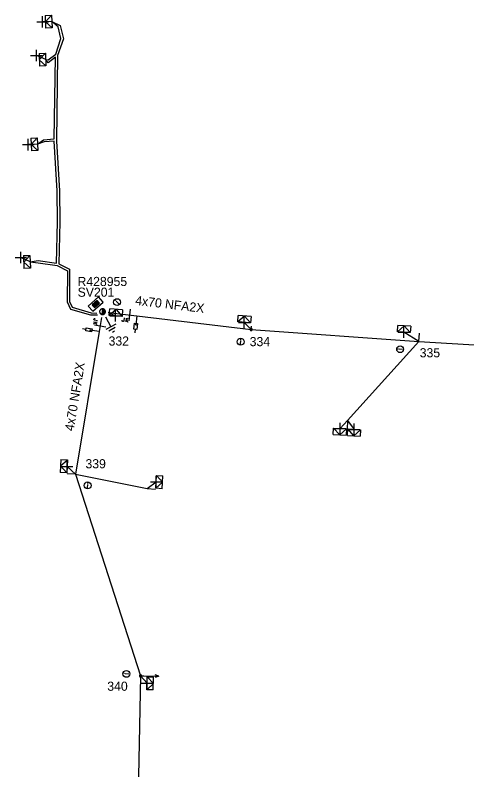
# Model space of a CAD drawing. Extents: x -540466 to -537383, y -1184038 to -1179972.
# Drawn here: x -538044.7 to -537995.3, y -1180805.5 to -1180723 of the extents above; entities that cross this region are included whole.
import ezdxf

# ---------------------------------------------------------------- set-up
doc = ezdxf.new("R2010")
doc.units = 0
for name, color, linetype in [('Vrstva 1', 7, 'Continuous'), ('Vrstva 10', 7, 'Continuous'), ('Vrstva 13', 7, 'Continuous'), ('Vrstva 14', 7, 'Continuous'), ('Vrstva 15', 7, 'Continuous'), ('Vrstva 16', 7, 'Continuous'), ('Vrstva 18', 7, 'Continuous'), ('Vrstva 2', 7, 'Continuous'), ('Vrstva 28', 7, 'Continuous'), ('Vrstva 29', 7, 'Continuous'), ('Vrstva 30', 7, 'Continuous'), ('Vrstva 31', 7, 'Continuous'), ('Vrstva 34', 7, 'Continuous'), ('Vrstva 36', 7, 'Continuous'), ('Vrstva 5', 7, 'Continuous'), ('Vrstva 50', 7, 'Continuous'), ('Vrstva 51', 7, 'Continuous'), ('Vrstva 59', 7, 'Continuous'), ('Vrstva 8', 7, 'Continuous'), ('Vrstva 9', 7, 'Continuous')]:
    doc.layers.add(name, color=color, linetype=linetype)

# ---------------------------------------------------------------- blocks, each defined once
blk = doc.blocks.new('NN440')
at = {"layer": 'Vrstva 2'}
for points in [[(0.63, 0), (0.63, 0.06), (0.62, 0.13), (0.6, 0.19), (0.58, 0.25), (0.55, 0.31), (0.51, 0.37), (0.47, 0.42), (0.42, 0.46), (0.37, 0.51), (0.32, 0.54), (0.26, 0.57), (0.2, 0.59), (0.13, 0.61), (0.07, 0.62), (0, 0.63), (-0.06, 0.62), (-0.13, 0.61), (-0.19, 0.59), (-0.26, 0.57), (-0.31, 0.54), (-0.37, 0.51), (-0.42, 0.46), (-0.47, 0.42), (-0.51, 0.37), (-0.54, 0.31), (-0.57, 0.25), (-0.6, 0.19), (-0.62, 0.13), (-0.63, 0.06), (-0.63, 0), (-0.63, -0.07), (-0.62, -0.14), (-0.6, -0.2), (-0.57, -0.26), (-0.54, -0.32), (-0.51, -0.37), (-0.47, -0.43), (-0.42, -0.47), (-0.37, -0.51), (-0.31, -0.55), (-0.26, -0.58), (-0.19, -0.6), (-0.13, -0.62), (-0.06, -0.63), (0, -0.63), (0.07, -0.63), (0.13, -0.62), (0.2, -0.6), (0.26, -0.58), (0.32, -0.55), (0.37, -0.51), (0.42, -0.47), (0.47, -0.43), (0.51, -0.37), (0.55, -0.32), (0.58, -0.26), (0.6, -0.2), (0.62, -0.14), (0.63, -0.07), (0.63, 0)], [(-0.63, 0), (0.63, 0)], [(-0.6, -0.18), (0.57, -0.18)], [(-0.51, -0.32), (0.5, -0.32)], [(-0.37, -0.47), (0.35, -0.47)]]:
    blk.add_lwpolyline(points, dxfattribs=at)
blk = doc.blocks.new('NN560')
at = {"layer": 'Vrstva 2'}
for points in [[(1.999, -0.001), (1.59, 0.141)], [(0, -0.001), (1.999, -0.001)], [(1.999, -0.001), (1.59, -0.134)]]:
    blk.add_lwpolyline(points, dxfattribs=at)
blk = doc.blocks.new('NN840')
at = {"layer": 'Vrstva 15'}
for points in [[(0.003, 0.619), (0.003, -0.631)], [(-0.745, -0.71), (-0.745, -0.66)], [(-0.73, -0.764), (-0.745, -0.71)], [(-0.657, -0.798), (-0.73, -0.764)], [(-0.627, -0.798), (-0.657, -0.798)], [(-0.558, -0.764), (-0.627, -0.798)], [(-0.538, -0.71), (-0.558, -0.764)], [(-0.538, -0.385), (-0.538, -0.71)], [(-0.332, -0.385), (-0.332, -0.798)], [(-0.332, -0.641), (-0.125, -0.385)], [(-0.263, -0.557), (-0.091, -0.798)]]:
    blk.add_lwpolyline(points, dxfattribs=at)
blk = doc.blocks.new('NN770')
at = {"layer": 'Vrstva 10'}
for p, q in [((0.002, 0.187), (0.002, 0.263)), ((0.002, -0.276), (0.002, 0.111))]:
    blk.add_line(p, q, dxfattribs=at)
blk.add_circle((0, -0.008), 0.375, dxfattribs=at)
blk = doc.blocks.new('NN800')
at = {"layer": 'Vrstva 1'}
for points in [[(-0.442, 0.442), (0.442, -0.442)], [(-0.442, -0.442), (0.442, 0.442)]]:
    blk.add_lwpolyline(points, dxfattribs=at)
blk = doc.blocks.new('NN820')
at = {"layer": 'Vrstva 13'}
for points in [[(-0.003, 0.004), (-0.003, -1.049)], [(-0.165, -0.813), (0.165, -0.813)], [(-0.165, -1.473), (-0.165, -0.813)], [(0.165, -0.813), (0.165, -1.473)], [(0.165, -1.473), (-0.165, -1.473)], [(-0.003, -1.049), (-0.062, -0.926)], [(-0.003, -1.049), (0.057, -0.926)], [(-0.003, -1.473), (-0.003, -1.871)]]:
    blk.add_lwpolyline(points, dxfattribs=at)
blk = doc.blocks.new('NN620')
at = {"layer": 'Vrstva 8'}
for points in [[(0.752, 0.004), (-0.748, 0.004)], [(-0.748, 0.004), (-0.748, -0.746)], [(0.752, -0.746), (0.752, 0.004)], [(-0.748, -0.746), (0.752, -0.746)], [(0.368, -0.18), (-0.376, -0.18)], [(-0.376, -0.18), (-0.376, -0.558)], [(-0.376, -0.558), (0.368, -0.558)], [(0.321, -0.227), (-0.329, -0.227)], [(-0.329, -0.227), (-0.329, -0.51)], [(-0.329, -0.51), (0.321, -0.51)], [(0.274, -0.274), (-0.281, -0.274)], [(-0.281, -0.274), (-0.281, -0.463)], [(-0.281, -0.463), (0.274, -0.463)], [(0.227, -0.321), (-0.234, -0.321)], [(-0.234, -0.321), (-0.234, -0.416)], [(-0.234, -0.416), (0.227, -0.416)], [(-0.193, -0.369), (0.185, -0.369)], [(0.227, -0.416), (0.227, -0.321)], [(0.274, -0.463), (0.274, -0.274)], [(0.321, -0.51), (0.321, -0.227)], [(0.368, -0.558), (0.368, -0.18)]]:
    blk.add_lwpolyline(points, dxfattribs=at)
blk = doc.blocks.new('NN630')
at = {"layer": 'Vrstva 9'}
for points in [[(-0.003, -0.7), (-0.703, 0)], [(-0.703, -0.7), (-0.703, 0), (0.697, 0), (0.697, -0.7)], [(-0.703, -0.7), (0.697, -0.7)], [(-0.003, -0.7), (0.697, 0)]]:
    blk.add_lwpolyline(points, dxfattribs=at)
blk = doc.blocks.new('NN810')
at = {"layer": 'Vrstva 14'}
for points in [[(0.004, -0.64), (0.004, -1.89)], [(0.629, -1.89), (-0.621, -1.89)], [(0.388, -2.2), (-0.399, -2.2)], [(0.004, -2.515), (-0.124, -2.515)], [(0.137, -2.515), (0.004, -2.515)]]:
    blk.add_lwpolyline(points, dxfattribs=at)
blk = doc.blocks.new('NN500')
at = {"layer": 'Vrstva 2'}
for points in [[(0, -0.24), (0.02, -0.23), (0.05, -0.23), (0.07, -0.22), (0.09, -0.22), (0.12, -0.2), (0.14, -0.19), (0.16, -0.18), (0.17, -0.16), (0.19, -0.14), (0.2, -0.12), (0.21, -0.1), (0.22, -0.07), (0.23, -0.05), (0.23, -0.02), (0.23, 0), (0.23, 0.02), (0.23, 0.05), (0.22, 0.07), (0.21, 0.1), (0.2, 0.12), (0.19, 0.14), (0.17, 0.16), (0.16, 0.17), (0.14, 0.19), (0.12, 0.2), (0.09, 0.21), (0.07, 0.22), (0.05, 0.23), (0.02, 0.23), (0, 0.23), (-0.03, 0.23), (-0.05, 0.23), (-0.07, 0.22), (-0.1, 0.21), (-0.12, 0.2), (-0.14, 0.19), (-0.16, 0.17), (-0.18, 0.16), (-0.19, 0.14), (-0.2, 0.12), (-0.22, 0.1), (-0.22, 0.07), (-0.23, 0.05), (-0.23, 0.02), (-0.24, 0), (-0.23, -0.02), (-0.23, -0.05), (-0.22, -0.07), (-0.22, -0.1), (-0.2, -0.12), (-0.19, -0.14), (-0.18, -0.16), (-0.16, -0.18), (-0.14, -0.19), (-0.12, -0.2), (-0.1, -0.22), (-0.07, -0.22), (-0.05, -0.23), (-0.03, -0.23), (0, -0.24)], [(0, -0.24), (0.02, -0.23), (0.05, -0.23), (0.07, -0.22), (0.09, -0.22), (0.12, -0.2), (0.14, -0.19), (0.16, -0.18), (0.17, -0.16), (0.19, -0.14), (0.2, -0.12), (0.21, -0.1), (0.22, -0.07), (0.23, -0.05), (0.23, -0.02), (0.23, 0), (0.23, 0.02), (0.23, 0.05), (0.22, 0.07), (0.21, 0.1), (0.2, 0.12), (0.19, 0.14), (0.17, 0.16), (0.16, 0.17), (0.14, 0.19), (0.12, 0.2), (0.09, 0.21), (0.07, 0.22), (0.05, 0.23), (0.02, 0.23), (0, 0.23), (-0.03, 0.23), (-0.05, 0.23), (-0.07, 0.22), (-0.1, 0.21), (-0.12, 0.2), (-0.14, 0.19), (-0.16, 0.17), (-0.18, 0.16), (-0.19, 0.14), (-0.2, 0.12), (-0.22, 0.1), (-0.22, 0.07), (-0.23, 0.05), (-0.23, 0.02), (-0.24, 0), (-0.23, -0.02), (-0.23, -0.05), (-0.22, -0.07), (-0.22, -0.1), (-0.2, -0.12), (-0.19, -0.14), (-0.18, -0.16), (-0.16, -0.18), (-0.14, -0.19), (-0.12, -0.2), (-0.1, -0.22), (-0.07, -0.22), (-0.05, -0.23), (-0.03, -0.23), (0, -0.24)], [(0, -0.21), (0.02, -0.2), (0.04, -0.2), (0.06, -0.2), (0.08, -0.19), (0.1, -0.18), (0.12, -0.17), (0.14, -0.15), (0.15, -0.14), (0.16, -0.12), (0.18, -0.1), (0.19, -0.08), (0.19, -0.06), (0.2, -0.04), (0.2, -0.02), (0.2, 0), (0.2, 0.02), (0.2, 0.04), (0.19, 0.06), (0.19, 0.08), (0.18, 0.1), (0.16, 0.12), (0.15, 0.14), (0.14, 0.15), (0.12, 0.17), (0.1, 0.18), (0.08, 0.19), (0.06, 0.19), (0.04, 0.2), (0.02, 0.2), (0, 0.2), (-0.02, 0.2), (-0.04, 0.2), (-0.06, 0.19), (-0.08, 0.19), (-0.1, 0.18), (-0.12, 0.17), (-0.14, 0.15), (-0.15, 0.14), (-0.17, 0.12), (-0.18, 0.1), (-0.19, 0.08), (-0.2, 0.06), (-0.2, 0.04), (-0.21, 0.02), (-0.21, 0), (-0.21, -0.02), (-0.2, -0.04), (-0.2, -0.06), (-0.19, -0.08), (-0.18, -0.1), (-0.17, -0.12), (-0.15, -0.14), (-0.14, -0.15), (-0.12, -0.17), (-0.1, -0.18), (-0.08, -0.19), (-0.06, -0.2), (-0.04, -0.2), (-0.02, -0.2), (0, -0.21)], [(0, -0.18), (0.02, -0.18), (0.04, -0.17), (0.05, -0.17), (0.07, -0.16), (0.09, -0.15), (0.1, -0.14), (0.12, -0.13), (0.13, -0.12), (0.14, -0.1), (0.15, -0.09), (0.16, -0.07), (0.17, -0.05), (0.17, -0.04), (0.17, -0.02), (0.17, 0), (0.17, 0.02), (0.17, 0.04), (0.17, 0.05), (0.16, 0.07), (0.15, 0.09), (0.14, 0.1), (0.13, 0.12), (0.12, 0.13), (0.1, 0.14), (0.09, 0.15), (0.07, 0.16), (0.05, 0.17), (0.04, 0.17), (0.02, 0.17), (0, 0.18), (-0.02, 0.17), (-0.04, 0.17), (-0.06, 0.17), (-0.07, 0.16), (-0.09, 0.15), (-0.1, 0.14), (-0.12, 0.13), (-0.13, 0.12), (-0.14, 0.1), (-0.15, 0.09), (-0.16, 0.07), (-0.17, 0.05), (-0.17, 0.04), (-0.18, 0.02), (-0.18, 0), (-0.18, -0.02), (-0.17, -0.04), (-0.17, -0.05), (-0.16, -0.07), (-0.15, -0.09), (-0.14, -0.1), (-0.13, -0.12), (-0.12, -0.13), (-0.1, -0.14), (-0.09, -0.15), (-0.07, -0.16), (-0.06, -0.17), (-0.04, -0.17), (-0.02, -0.18), (0, -0.18)], [(0, -0.15), (0.01, -0.15), (0.03, -0.14), (0.04, -0.14), (0.06, -0.13), (0.07, -0.13), (0.08, -0.12), (0.1, -0.11), (0.11, -0.1), (0.12, -0.09), (0.13, -0.07), (0.13, -0.06), (0.14, -0.05), (0.14, -0.03), (0.14, -0.02), (0.14, 0), (0.14, 0.01), (0.14, 0.03), (0.14, 0.04), (0.13, 0.06), (0.13, 0.07), (0.12, 0.09), (0.11, 0.1), (0.1, 0.11), (0.08, 0.12), (0.07, 0.13), (0.06, 0.13), (0.04, 0.14), (0.03, 0.14), (0.01, 0.14), (0, 0.15), (-0.02, 0.14), (-0.03, 0.14), (-0.05, 0.14), (-0.06, 0.13), (-0.07, 0.13), (-0.09, 0.12), (-0.1, 0.11), (-0.11, 0.1), (-0.12, 0.09), (-0.13, 0.07), (-0.13, 0.06), (-0.14, 0.04), (-0.14, 0.03), (-0.15, 0.01), (-0.15, 0), (-0.15, -0.02), (-0.14, -0.03), (-0.14, -0.05), (-0.13, -0.06), (-0.13, -0.07), (-0.12, -0.09), (-0.11, -0.1), (-0.1, -0.11), (-0.09, -0.12), (-0.07, -0.13), (-0.06, -0.13), (-0.05, -0.14), (-0.03, -0.14), (-0.02, -0.15), (0, -0.15)], [(0, -0.12), (0.01, -0.12), (0.02, -0.11), (0.03, -0.11), (0.05, -0.11), (0.06, -0.1), (0.07, -0.09), (0.08, -0.09), (0.09, -0.08), (0.09, -0.07), (0.1, -0.06), (0.11, -0.05), (0.11, -0.04), (0.11, -0.02), (0.11, -0.01), (0.12, 0), (0.11, 0.01), (0.11, 0.02), (0.11, 0.04), (0.11, 0.05), (0.1, 0.06), (0.09, 0.07), (0.09, 0.08), (0.08, 0.09), (0.07, 0.09), (0.06, 0.1), (0.05, 0.11), (0.03, 0.11), (0.02, 0.11), (0.01, 0.12), (0, 0.12), (-0.01, 0.12), (-0.03, 0.11), (-0.04, 0.11), (-0.05, 0.11), (-0.06, 0.1), (-0.07, 0.09), (-0.08, 0.09), (-0.09, 0.08), (-0.1, 0.07), (-0.1, 0.06), (-0.11, 0.05), (-0.11, 0.04), (-0.12, 0.02), (-0.12, 0.01), (-0.12, 0), (-0.12, -0.01), (-0.12, -0.02), (-0.11, -0.04), (-0.11, -0.05), (-0.1, -0.06), (-0.1, -0.07), (-0.09, -0.08), (-0.08, -0.09), (-0.07, -0.09), (-0.06, -0.1), (-0.05, -0.11), (-0.04, -0.11), (-0.03, -0.11), (-0.01, -0.12), (0, -0.12)], [(0, -0.09), (0.01, -0.09), (0.02, -0.09), (0.03, -0.08), (0.03, -0.08), (0.04, -0.08), (0.05, -0.07), (0.06, -0.07), (0.06, -0.06), (0.07, -0.05), (0.07, -0.04), (0.08, -0.04), (0.08, -0.03), (0.08, -0.02), (0.09, -0.01), (0.09, 0), (0.09, 0.01), (0.08, 0.02), (0.08, 0.03), (0.08, 0.03), (0.07, 0.04), (0.07, 0.05), (0.06, 0.06), (0.06, 0.06), (0.05, 0.07), (0.04, 0.07), (0.03, 0.08), (0.03, 0.08), (0.02, 0.08), (0.01, 0.09), (0, 0.09), (-0.01, 0.09), (-0.02, 0.08), (-0.03, 0.08), (-0.04, 0.08), (-0.04, 0.07), (-0.05, 0.07), (-0.06, 0.06), (-0.07, 0.06), (-0.07, 0.05), (-0.08, 0.04), (-0.08, 0.03), (-0.08, 0.03), (-0.09, 0.02), (-0.09, 0.01), (-0.09, 0), (-0.09, -0.01), (-0.09, -0.02), (-0.08, -0.03), (-0.08, -0.04), (-0.08, -0.04), (-0.07, -0.05), (-0.07, -0.06), (-0.06, -0.07), (-0.05, -0.07), (-0.04, -0.08), (-0.04, -0.08), (-0.03, -0.08), (-0.02, -0.09), (-0.01, -0.09), (0, -0.09)], [(0, -0.06), (0, -0.06), (0.01, -0.06), (0.02, -0.05), (0.02, -0.05), (0.03, -0.05), (0.03, -0.05), (0.04, -0.04), (0.04, -0.04), (0.05, -0.03), (0.05, -0.03), (0.05, -0.02), (0.05, -0.02), (0.05, -0.01), (0.06, -0.01), (0.06, 0), (0.06, 0.01), (0.05, 0.01), (0.05, 0.02), (0.05, 0.02), (0.05, 0.03), (0.05, 0.03), (0.04, 0.04), (0.04, 0.04), (0.03, 0.05), (0.03, 0.05), (0.02, 0.05), (0.02, 0.05), (0.01, 0.06), (0, 0.06), (0, 0.06), (-0.01, 0.06), (-0.01, 0.06), (-0.02, 0.05), (-0.02, 0.05), (-0.03, 0.05), (-0.03, 0.05), (-0.04, 0.04), (-0.04, 0.04), (-0.05, 0.03), (-0.05, 0.03), (-0.05, 0.02), (-0.06, 0.02), (-0.06, 0.01), (-0.06, 0.01), (-0.06, 0), (-0.06, -0.01), (-0.06, -0.01), (-0.06, -0.02), (-0.05, -0.02), (-0.05, -0.03), (-0.05, -0.03), (-0.04, -0.04), (-0.04, -0.04), (-0.03, -0.05), (-0.03, -0.05), (-0.02, -0.05), (-0.02, -0.05), (-0.01, -0.06), (-0.01, -0.06), (0, -0.06)], [(0, -0.03), (0, -0.03), (0, -0.03), (0.01, -0.03), (0.01, -0.03), (0.01, -0.02), (0.02, -0.02), (0.02, -0.02), (0.02, -0.02), (0.02, -0.02), (0.02, -0.01), (0.02, -0.01), (0.03, -0.01), (0.03, -0.01), (0.03, 0), (0.03, 0), (0.03, 0), (0.03, 0.01), (0.03, 0.01), (0.02, 0.01), (0.02, 0.01), (0.02, 0.02), (0.02, 0.02), (0.02, 0.02), (0.02, 0.02), (0.01, 0.02), (0.01, 0.02), (0.01, 0.03), (0, 0.03), (0, 0.03), (0, 0.03), (0, 0.03), (-0.01, 0.03), (-0.01, 0.03), (-0.01, 0.02), (-0.02, 0.02), (-0.02, 0.02), (-0.02, 0.02), (-0.02, 0.02), (-0.02, 0.02), (-0.03, 0.01), (-0.03, 0.01), (-0.03, 0.01), (-0.03, 0.01), (-0.03, 0), (-0.03, 0), (-0.03, 0), (-0.03, -0.01), (-0.03, -0.01), (-0.03, -0.01), (-0.03, -0.01), (-0.02, -0.02), (-0.02, -0.02), (-0.02, -0.02), (-0.02, -0.02), (-0.02, -0.02), (-0.01, -0.03), (-0.01, -0.03), (-0.01, -0.03), (0, -0.03), (0, -0.03)], [(0.23, 0), (0.7, 0)]]:
    blk.add_lwpolyline(points, dxfattribs=at)
blk = doc.blocks.new('NN510')
at = {"layer": 'Vrstva 2'}
blk.add_lwpolyline([(0.001, 0.002), (0.001, 0.939)], dxfattribs=at)

msp = doc.modelspace()

# ---------------------------------------------------------------- linework, layer by layer
at = {"layer": 'Vrstva 5'}
for points in [[(-538041.31, -1180727.84), (-538041.035, -1180727.876), (-538040.216, -1180727.244), (-538039.64, -1180725.544), (-538039.94, -1180724.268), (-538040.647, -1180723.681), (-538039.72, -1180724.112), (-538039.38, -1180725.556), (-538040.004, -1180727.396), (-538040.127, -1180736.746), (-538039.815, -1180742.186), (-538039.775, -1180745.591), (-538039.873, -1180750.165), (-538038.69, -1180750.77), (-538038.705, -1180754.273), (-538038.41, -1180754.906), (-538036.352, -1180755.518), (-538035.717, -1180755.55)], [(-538043.013, -1180749.952), (-538042.123, -1180749.805), (-538040.122, -1180750.096), (-538040.025, -1180745.589), (-538040.065, -1180742.194), (-538040.366, -1180736.771), (-538041.466, -1180736.843), (-538042.21, -1180737.08), (-538041.534, -1180736.597), (-538040.373, -1180736.514), (-538040.243, -1180727.573), (-538041.025, -1180728.184), (-538041.31, -1180727.84)], [(-538043.013, -1180749.952), (-538042.137, -1180750.055), (-538040.04, -1180750.36), (-538038.916, -1180750.945), (-538038.955, -1180754.327), (-538038.59, -1180755.114), (-538036.408, -1180755.762), (-538035.63, -1180755.758)]]:
    msp.add_lwpolyline(points, dxfattribs=at)
at = {"layer": 'Vrstva 50'}
for points in [[(-538034.468, -1180755.477), (-538031.337, -1180755.85), (-538018.847, -1180757.341), (-538000.519, -1180758.677), (-537985.932, -1180759.534)], [(-538035.202, -1180756.021), (-538035.459, -1180757.579), (-538038.038, -1180773.166), (-538030.938, -1180795.212), (-538031.319, -1180813.535), (-538031.082, -1180834.986)]]:
    msp.add_lwpolyline(points, dxfattribs=at)
at = {"layer": 'Vrstva 59'}
for points in [[(-538040.647, -1180723.681), (-538041.646, -1180723.726)], [(-538041.31, -1180727.84), (-538042.331, -1180727.386)], [(-538042.21, -1180737.08), (-538043.208, -1180737.141)], [(-538043.013, -1180749.952), (-538044.03, -1180749.488)], [(-538008.304, -1180767.291), (-538009.13, -1180768.174)], [(-538008.304, -1180767.291), (-538007.579, -1180768.264)]]:
    msp.add_lwpolyline(points, dxfattribs=at)
at = {"layer": 'Vrstva 8'}
for points in [[(-538034.468, -1180755.477), (-538033.666, -1180755.855)], [(-538018.847, -1180757.341), (-538019.615, -1180756.572)], [(-538000.519, -1180758.677), (-538002.15, -1180757.64)], [(-538000.519, -1180758.677), (-538008.304, -1180767.291)], [(-538038.038, -1180773.166), (-538038.978, -1180772.307)], [(-538038.038, -1180773.166), (-538030.235, -1180774.743), (-538029.237, -1180774.002)], [(-538030.938, -1180795.212), (-538030.231, -1180796.016)]]:
    msp.add_lwpolyline(points, dxfattribs=at)

# ---------------------------------------------------------------- block references
at = {"layer": 'Vrstva 13'}
for name, p, xscale, yscale, rotation in [('NN440', (-538035.1, -1180755.402), 0.5, 0.49999999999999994, 82.11889440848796), ('NN500', (-538018.847, -1180757.341), 0.5000000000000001, 0.5, 85.73899999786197), ('NN500', (-538030.938, -1180795.212), 0.49999999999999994, 0.5000000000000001, -1.2830000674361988)]:
    msp.add_blockref(name, p, dxfattribs=dict(at, xscale=xscale, yscale=yscale, rotation=rotation))
for name, p, rotation in [('NN510', (-538000.52, -1180758.677), -3.3748166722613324), ('NN510', (-538008.303, -1180767.291), 176.62620553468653), ('NN510', (-538038.037, -1180773.166), 86.772808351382), ('NN510', (-538030.235, -1180774.742), -93.71436383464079), ('NN560', (-538030.938, -1180795.212), -1.2833972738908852)]:
    msp.add_blockref(name, p, dxfattribs=dict(at, rotation=rotation))
at = {"layer": 'Vrstva 15', "rotation": 28.64399734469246}
msp.add_blockref('NN810', (-538035.1, -1180755.402), dxfattribs=at)
at = {"layer": 'Vrstva 16'}
for p, rotation in [((-538031.337, -1180755.85), -6.804733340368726), ((-538035.459, -1180757.579), -99.39240003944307)]:
    msp.add_blockref('NN820', p, dxfattribs=dict(at, rotation=rotation))
at = {"layer": 'Vrstva 18'}
for p, rotation in [((-538032.137, -1180755.755), -6.804733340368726), ((-538035.361, -1180756.986), -99.39240001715)]:
    msp.add_blockref('NN840', p, dxfattribs=dict(at, rotation=rotation))
at = {"layer": 'Vrstva 28', "rotation": -138.46799989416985}
msp.add_blockref('NN620', (-538035.598, -1180754.84), dxfattribs=at)
at = {"layer": 'Vrstva 31'}
for p, rotation in [((-538040.647, -1180723.681), -87.41965561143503), ((-538041.31, -1180727.84), -87.41965554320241), ((-538042.21, -1180737.08), -86.53876669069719), ((-538043.013, -1180749.952), -87.9798750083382), ((-538033.666, -1180755.855), 175.57718331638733), ((-538019.615, -1180756.572), 175.73921938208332), ((-538002.15, -1180757.64), 176.71228606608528), ((-538009.13, -1180768.174), -3.267038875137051), ((-538007.579, -1180768.264), -3.373794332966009), ((-538038.978, -1180772.307), -93.22719164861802), ((-538029.237, -1180774.002), 86.28563616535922), ((-538030.231, -1180796.016), 88.71660279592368)]:
    msp.add_blockref('NN630', p, dxfattribs=dict(at, rotation=rotation))
at = {"layer": 'Vrstva 34'}
for p, rotation in [((-538041.646, -1180723.726), 44.99999995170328), ((-538042.331, -1180727.386), 45.00000009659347), ((-538043.208, -1180737.141), 45), ((-538044.03, -1180749.488), 45), ((-538033.666, -1180755.855), 45), ((-538019.615, -1180756.572), 45), ((-538002.15, -1180757.64), 45), ((-538009.13, -1180768.174), 45), ((-538007.579, -1180768.264), 45), ((-538038.978, -1180772.307), 45), ((-538029.237, -1180774.002), 45), ((-538030.231, -1180796.016), 45)]:
    msp.add_blockref('NN800', p, dxfattribs=dict(at, rotation=rotation))
at = {"layer": 'Vrstva 36'}
for p, rotation in [((-538033.516, -1180754.348), 41.53206668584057), ((-538019.997, -1180758.67), -2.2906110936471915), ((-538002.571, -1180759.504), 86.63712777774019), ((-538036.729, -1180774.384), -3.2408528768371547), ((-538032.497, -1180794.99), 80.53767779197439)]:
    msp.add_blockref('NN770', p, dxfattribs=dict(at, rotation=rotation))

# ---------------------------------------------------------------- texts
at = {"layer": 'Vrstva 14'}
for s, p in [('332', (-538034.434, -1180759.106)), ('334', (-538019.008, -1180759.171)), ('335', (-538000.424, -1180760.392)), ('339', (-538036.962, -1180772.524)), ('340', (-538034.576, -1180796.839))]:
    msp.add_text(s, height=1, dxfattribs=at).set_placement(p)
at = {"layer": 'Vrstva 29'}
msp.add_text('R428955', height=1, dxfattribs=at).set_placement((-538037.833, -1180752.598))
at = {"layer": 'Vrstva 30'}
msp.add_text('SV201', height=1, dxfattribs=at).set_placement((-538037.82, -1180753.768))
at = {"layer": 'Vrstva 51'}
for rotation, p in [(353.193, (-538031.559, -1180754.639)), (80.605, (-538038.257, -1180768.5))]:
    msp.add_text('4x70 NFA2X', height=1, rotation=rotation, dxfattribs=at).set_placement(p)

doc.saveas('drawing.dxf')
